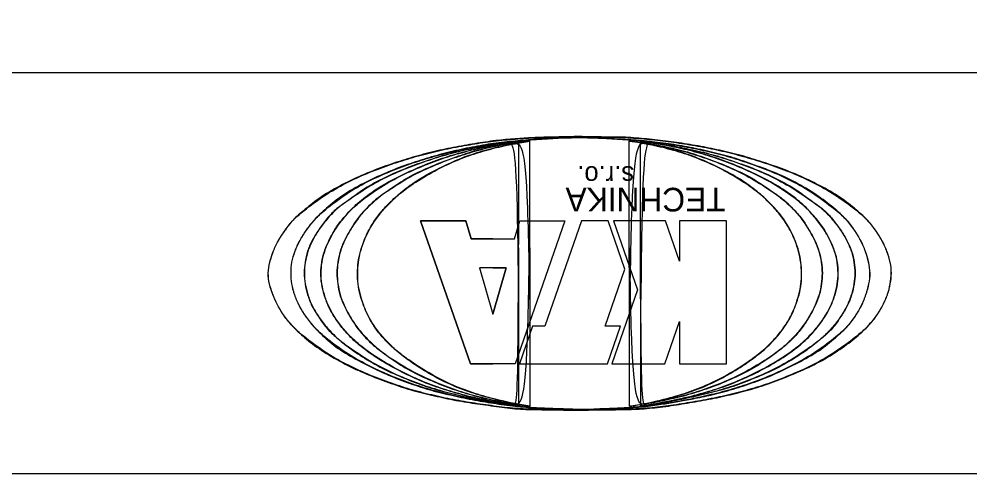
# Model space of a CAD drawing. Extents: x -728452 to -728347, y -1073107 to -1072959.
# Drawn here: x -728436.11 to -728412.4, y -1073034.8 to -1073023.46 of the extents above; entities that cross this region are included whole.
import ezdxf

# ---------------------------------------------------------------- set-up
doc = ezdxf.new("R2010")
doc.units = 0
doc.layers.add('Dočasný_nad_1_rok', color=7, linetype='Continuous')
doc.layers.add('Dočasný_nad_1_rok_PUPFL', color=7, linetype='Continuous')

msp = doc.modelspace()

# ---------------------------------------------------------------- linework, layer by layer
at = {"layer": 'Dočasný_nad_1_rok'}
msp.add_line((-728424.294, -1073032.056), (-728424.851, -1073032.056), dxfattribs=at)
for points in [[(-728424.294, -1073028.942), (-728424.836, -1073028.942), (-728424.968, -1073028.486), (-728426.094, -1073028.487), (-728424.851, -1073032.056), (-728424.294, -1073032.056)], [(-728424.851, -1073032.056), (-728426.094, -1073028.487), (-728424.968, -1073028.486), (-728424.836, -1073028.942), (-728424.294, -1073028.942)], [(-728424.294, -1073028.942), (-728423.753, -1073028.942), (-728423.621, -1073028.486), (-728422.495, -1073028.487), (-728423.738, -1073032.056), (-728424.294, -1073032.056)], [(-728424.294, -1073028.942), (-728423.753, -1073028.942), (-728423.621, -1073028.486), (-728422.495, -1073028.487), (-728423.738, -1073032.056), (-728424.294, -1073032.056)], [(-728421.435, -1073032.056), (-728421.107, -1073031.113), (-728421.495, -1073031.113), (-728421.001, -1073029.693), (-728421.421, -1073028.486), (-728422.085, -1073028.486), (-728423, -1073031.113), (-728423.302, -1073031.113), (-728423.63, -1073032.056), (-728421.435, -1073032.056)], [(-728421.435, -1073032.056), (-728421.107, -1073031.113), (-728421.495, -1073031.113), (-728421.001, -1073029.693), (-728421.421, -1073028.486), (-728422.085, -1073028.486), (-728423, -1073031.113), (-728423.302, -1073031.113), (-728423.63, -1073032.056), (-728421.435, -1073032.056)], [(-728418.466, -1073032.056), (-728418.466, -1073028.486), (-728419.635, -1073028.486), (-728419.635, -1073029.492), (-728419.985, -1073028.486), (-728421.285, -1073028.486), (-728420.685, -1073030.209), (-728421.328, -1073032.056), (-728420.003, -1073032.056), (-728419.635, -1073030.998), (-728419.635, -1073032.056), (-728418.466, -1073032.056)], [(-728418.466, -1073032.056), (-728418.466, -1073028.486), (-728419.635, -1073028.486), (-728419.635, -1073029.492), (-728419.985, -1073028.486), (-728421.285, -1073028.486), (-728420.685, -1073030.209), (-728421.328, -1073032.056), (-728420.003, -1073032.056), (-728419.635, -1073030.998), (-728419.635, -1073032.056), (-728418.466, -1073032.056)], [(-728424.294, -1073029.665), (-728424.626, -1073029.665), (-728424.294, -1073030.813)], [(-728424.294, -1073029.665), (-728424.626, -1073029.665), (-728424.294, -1073030.813)], [(-728424.294, -1073029.665), (-728423.962, -1073029.665), (-728424.294, -1073030.813)], [(-728424.294, -1073030.813), (-728423.962, -1073029.665), (-728424.294, -1073029.665)]]:
    msp.add_lwpolyline(points, dxfattribs=at)
for points in [[(-728423.358, -1073026.421), (-728423.485, -1073026.428), (-728423.79, -1073026.45), (-728424.276, -1073026.491), (-728424.81, -1073026.579), (-728425.348, -1073026.67), (-728425.885, -1073026.792), (-728426.423, -1073026.94), (-728426.96, -1073027.117), (-728427.498, -1073027.323), (-728428.038, -1073027.576), (-728428.59, -1073027.889), (-728428.983, -1073028.211), (-728429.3, -1073028.476), (-728429.469, -1073028.716), (-728429.656, -1073028.975), (-728429.776, -1073029.251), (-728429.866, -1073029.519), (-728429.918, -1073029.791), (-728429.881, -1073030.068), (-728429.779, -1073030.334), (-728429.665, -1073030.608), (-728429.497, -1073030.882), (-728429.302, -1073031.107), (-728429, -1073031.403), (-728428.589, -1073031.714), (-728428.042, -1073032.034), (-728427.504, -1073032.292), (-728426.96, -1073032.493), (-728426.428, -1073032.686), (-728425.885, -1073032.82), (-728425.349, -1073032.944), (-728424.808, -1073033.035), (-728424.271, -1073033.105), (-728423.738, -1073033.188), (-728423.202, -1073033.194), (-728422.666, -1073033.205), (-728422.309, -1073033.208), (-728422.13, -1073033.209)], [(-728422.13, -1073033.209), (-728421.524, -1073033.201), (-728421.057, -1073033.194), (-728420.521, -1073033.172), (-728419.985, -1073033.116), (-728419.45, -1073033.032), (-728418.912, -1073032.939), (-728418.377, -1073032.824), (-728417.841, -1073032.684), (-728417.303, -1073032.509), (-728416.767, -1073032.295), (-728416.234, -1073032.049), (-728415.697, -1073031.731), (-728415.161, -1073031.327), (-728414.953, -1073031.133), (-728414.734, -1073030.864), (-728414.572, -1073030.597), (-728414.451, -1073030.328), (-728414.386, -1073030.061), (-728414.356, -1073029.793), (-728414.384, -1073029.529), (-728414.465, -1073029.258), (-728414.586, -1073028.988), (-728414.754, -1073028.722), (-728414.97, -1073028.453), (-728415.161, -1073028.274), (-728415.697, -1073027.868), (-728416.233, -1073027.565), (-728416.763, -1073027.318), (-728417.305, -1073027.113), (-728417.843, -1073026.939), (-728418.376, -1073026.793), (-728418.909, -1073026.675), (-728419.447, -1073026.577), (-728419.985, -1073026.501), (-728420.523, -1073026.442), (-728421.054, -1073026.406), (-728421.594, -1073026.4), (-728422.13, -1073026.391), (-728422.666, -1073026.4), (-728423.203, -1073026.414), (-728423.739, -1073026.447), (-728424.272, -1073026.498), (-728424.81, -1073026.579), (-728425.345, -1073026.674), (-728425.881, -1073026.795), (-728426.419, -1073026.944), (-728426.955, -1073027.12), (-728427.491, -1073027.328), (-728428.024, -1073027.577), (-728428.564, -1073027.893), (-728429.103, -1073028.311), (-728429.263, -1073028.454), (-728429.473, -1073028.72), (-728429.65, -1073028.987), (-728429.774, -1073029.257), (-728429.861, -1073029.524), (-728429.904, -1073029.793), (-728429.872, -1073030.06), (-728429.78, -1073030.329), (-728429.659, -1073030.603), (-728429.499, -1073030.864), (-728429.272, -1073031.133), (-728429.106, -1073031.296), (-728428.565, -1073031.715), (-728428.029, -1073032.032), (-728427.496, -1073032.286), (-728426.958, -1073032.493), (-728426.419, -1073032.678), (-728425.886, -1073032.818), (-728425.346, -1073032.939), (-728424.807, -1073033.031), (-728424.268, -1073033.107), (-728423.737, -1073033.175), (-728423.202, -1073033.194), (-728422.667, -1073033.204), (-728422.13, -1073033.209), (-728422.13, -1073033.209), (-728422.13, -1073033.209)], [(-728422.13, -1073033.194), (-728422.309, -1073033.187), (-728422.666, -1073033.173), (-728423.204, -1073033.167), (-728423.739, -1073033.109), (-728424.275, -1073033.04), (-728424.813, -1073032.951), (-728425.348, -1073032.833), (-728425.889, -1073032.704), (-728426.424, -1073032.522), (-728426.965, -1073032.316), (-728427.499, -1073032.051), (-728428.056, -1073031.752), (-728428.468, -1073031.424), (-728428.773, -1073031.118), (-728428.965, -1073030.876), (-728429.13, -1073030.605), (-728429.252, -1073030.336), (-728429.316, -1073030.062), (-728429.34, -1073029.792), (-728429.319, -1073029.519), (-728429.238, -1073029.25), (-728429.118, -1073028.979), (-728428.946, -1073028.711), (-728428.764, -1073028.473), (-728428.455, -1073028.183), (-728428.056, -1073027.853), (-728427.503, -1073027.541), (-728426.962, -1073027.291), (-728426.424, -1073027.082), (-728425.885, -1073026.913), (-728425.349, -1073026.764), (-728424.811, -1073026.653), (-728424.275, -1073026.555), (-728423.737, -1073026.502), (-728423.202, -1073026.456), (-728422.666, -1073026.422), (-728422.13, -1073026.404), (-728421.593, -1073026.424), (-728421.057, -1073026.463), (-728420.52, -1073026.492), (-728419.983, -1073026.556), (-728419.446, -1073026.643), (-728418.909, -1073026.756), (-728418.37, -1073026.889), (-728417.837, -1073027.074), (-728417.295, -1073027.268), (-728416.752, -1073027.514), (-728416.213, -1073027.841), (-728415.79, -1073028.162), (-728415.467, -1073028.457), (-728415.274, -1073028.709), (-728415.114, -1073028.981), (-728414.994, -1073029.251), (-728414.919, -1073029.521), (-728414.872, -1073029.792), (-728414.913, -1073030.064), (-728414.983, -1073030.335), (-728415.096, -1073030.606), (-728415.255, -1073030.875), (-728415.448, -1073031.139), (-728415.783, -1073031.437), (-728416.206, -1073031.773), (-728416.761, -1073032.069), (-728417.295, -1073032.329), (-728417.834, -1073032.538), (-728418.372, -1073032.71), (-728418.91, -1073032.848), (-728419.368, -1073032.939), (-728419.726, -1073033.004), (-728420.083, -1073033.062), (-728420.52, -1073033.126), (-728421.057, -1073033.16), (-728421.593, -1073033.182), (-728421.951, -1073033.19), (-728422.13, -1073033.194)], [(-728422.13, -1073033.194), (-728421.593, -1073033.18), (-728421.057, -1073033.158), (-728420.522, -1073033.119), (-728419.986, -1073033.046), (-728419.744, -1073033.006), (-728419.45, -1073032.953), (-728418.913, -1073032.843), (-728418.377, -1073032.706), (-728417.84, -1073032.534), (-728417.304, -1073032.324), (-728416.767, -1073032.068), (-728416.234, -1073031.768), (-728415.698, -1073031.358), (-728415.459, -1073031.133), (-728415.254, -1073030.864), (-728415.1, -1073030.598), (-728414.987, -1073030.328), (-728414.917, -1073030.061), (-728414.886, -1073029.792), (-728414.923, -1073029.525), (-728414.999, -1073029.258), (-728415.116, -1073028.989), (-728415.274, -1073028.721), (-728415.484, -1073028.452), (-728415.698, -1073028.25), (-728416.233, -1073027.841), (-728416.767, -1073027.52), (-728417.303, -1073027.273), (-728417.839, -1073027.074), (-728418.376, -1073026.896), (-728418.912, -1073026.759), (-728419.448, -1073026.647), (-728419.985, -1073026.559), (-728420.521, -1073026.498), (-728421.057, -1073026.461), (-728421.594, -1073026.427), (-728422.13, -1073026.41), (-728422.665, -1073026.424), (-728423.203, -1073026.458), (-728423.736, -1073026.503), (-728424.272, -1073026.562), (-728424.809, -1073026.655), (-728425.345, -1073026.77), (-728425.881, -1073026.915), (-728426.419, -1073027.087), (-728426.955, -1073027.294), (-728427.49, -1073027.544), (-728428.028, -1073027.857), (-728428.563, -1073028.286), (-728428.735, -1073028.453), (-728428.948, -1073028.722), (-728429.114, -1073028.988), (-728429.234, -1073029.257), (-728429.31, -1073029.524), (-728429.333, -1073029.79), (-728429.31, -1073030.06), (-728429.246, -1073030.327), (-728429.128, -1073030.596), (-728428.965, -1073030.864), (-728428.752, -1073031.133), (-728428.564, -1073031.324), (-728428.028, -1073031.747), (-728427.491, -1073032.052), (-728426.955, -1073032.31), (-728426.419, -1073032.52), (-728425.882, -1073032.697), (-728425.346, -1073032.832), (-728424.81, -1073032.947), (-728424.273, -1073033.037), (-728423.737, -1073033.107), (-728423.203, -1073033.159), (-728422.667, -1073033.175), (-728422.13, -1073033.194), (-728422.13, -1073033.194), (-728422.13, -1073033.194)], [(-728423.648, -1073026.51), (-728423.751, -1073026.519), (-728423.961, -1073026.536), (-728424.35, -1073026.596), (-728424.815, -1073026.691), (-728425.357, -1073026.807), (-728425.891, -1073026.978), (-728426.43, -1073027.164), (-728426.97, -1073027.397), (-728427.517, -1073027.69), (-728427.898, -1073027.991), (-728428.237, -1073028.214), (-728428.437, -1073028.44), (-728428.642, -1073028.713), (-728428.801, -1073028.982), (-728428.924, -1073029.247), (-728428.979, -1073029.522), (-728429.009, -1073029.792), (-728428.98, -1073030.063), (-728428.918, -1073030.335), (-728428.813, -1073030.61), (-728428.647, -1073030.872), (-728428.455, -1073031.156), (-728428.236, -1073031.366), (-728427.915, -1073031.628), (-728427.512, -1073031.91), (-728426.969, -1073032.216), (-728426.426, -1073032.444), (-728425.891, -1073032.648), (-728425.351, -1073032.793), (-728424.81, -1073032.914), (-728424.275, -1073033.021), (-728423.887, -1073033.09), (-728423.678, -1073033.102), (-728423.65, -1073033.104)], [(-728423.648, -1073026.51), (-728423.956, -1073026.539), (-728424.277, -1073026.586), (-728424.813, -1073026.691), (-728425.352, -1073026.815), (-728425.889, -1073026.979), (-728426.423, -1073027.168), (-728426.956, -1073027.4), (-728427.494, -1073027.698), (-728428.033, -1073028.079), (-728428.178, -1073028.181), (-728428.441, -1073028.452), (-728428.644, -1073028.726), (-728428.799, -1073028.989), (-728428.914, -1073029.254), (-728428.975, -1073029.526), (-728428.999, -1073029.794), (-728428.975, -1073030.057), (-728428.912, -1073030.33), (-728428.807, -1073030.6), (-728428.649, -1073030.865), (-728428.457, -1073031.133), (-728428.184, -1073031.406), (-728428.037, -1073031.527), (-728427.494, -1073031.909), (-728426.953, -1073032.211), (-728426.418, -1073032.443), (-728425.89, -1073032.638), (-728425.342, -1073032.791), (-728424.811, -1073032.912), (-728424.272, -1073033.02), (-728423.734, -1073033.099), (-728423.65, -1073033.104), (-728423.648, -1073026.51), (-728423.65, -1073033.104)], [(-728423.65, -1073033.104), (-728423.843, -1073033.075), (-728424.232, -1073033.017), (-728424.8, -1073032.9), (-728425.353, -1073032.748), (-728425.893, -1073032.569), (-728426.429, -1073032.333), (-728426.97, -1073032.049), (-728427.444, -1073031.74), (-728427.816, -1073031.429), (-728428.064, -1073031.143), (-728428.258, -1073030.877), (-728428.403, -1073030.606), (-728428.506, -1073030.335), (-728428.568, -1073030.063), (-728428.586, -1073029.791), (-728428.567, -1073029.521), (-728428.499, -1073029.25), (-728428.383, -1073028.983), (-728428.242, -1073028.708), (-728428.04, -1073028.443), (-728427.796, -1073028.165), (-728427.436, -1073027.855), (-728426.97, -1073027.551), (-728426.426, -1073027.277), (-728425.887, -1073027.048), (-728425.352, -1073026.857), (-728424.814, -1073026.713), (-728424.328, -1073026.614), (-728423.939, -1073026.55), (-728423.73, -1073026.521), (-728423.648, -1073026.51)], [(-728423.65, -1073033.104), (-728424.229, -1073033.012), (-728424.81, -1073032.891), (-728425.349, -1073032.744), (-728425.887, -1073032.562), (-728426.418, -1073032.331), (-728426.954, -1073032.047), (-728427.491, -1073031.691), (-728427.828, -1073031.402), (-728428.067, -1073031.131), (-728428.256, -1073030.866), (-728428.398, -1073030.601), (-728428.501, -1073030.329), (-728428.562, -1073030.058), (-728428.58, -1073029.793), (-728428.559, -1073029.523), (-728428.493, -1073029.257), (-728428.383, -1073028.99), (-728428.238, -1073028.719), (-728428.044, -1073028.454), (-728427.804, -1073028.186), (-728427.486, -1073027.908), (-728426.955, -1073027.556), (-728426.416, -1073027.28), (-728425.881, -1073027.052), (-728425.345, -1073026.863), (-728424.811, -1073026.718), (-728424.274, -1073026.607), (-728423.893, -1073026.544), (-728423.648, -1073026.51), (-728423.65, -1073033.104), (-728423.648, -1073026.51)], [(-728423.369, -1073026.502), (-728423.492, -1073026.512), (-728423.797, -1073026.539), (-728424.276, -1073026.641), (-728424.817, -1073026.763), (-728425.35, -1073026.948), (-728425.891, -1073027.156), (-728426.44, -1073027.416), (-728426.844, -1073027.702), (-728427.203, -1073027.939), (-728427.44, -1073028.174), (-728427.683, -1073028.436), (-728427.849, -1073028.718), (-728428.003, -1073028.98), (-728428.106, -1073029.25), (-728428.163, -1073029.52), (-728428.193, -1073029.791), (-728428.16, -1073030.062), (-728428.118, -1073030.335), (-728428.007, -1073030.604), (-728427.864, -1073030.871), (-728427.69, -1073031.146), (-728427.463, -1073031.42), (-728427.207, -1073031.648), (-728426.858, -1073031.911), (-728426.436, -1073032.188), (-728425.893, -1073032.454), (-728425.354, -1073032.664), (-728424.818, -1073032.84), (-728424.278, -1073032.963), (-728423.797, -1073033.062), (-728423.492, -1073033.097), (-728423.369, -1073033.111)], [(-728423.369, -1073026.502), (-728423.737, -1073026.54), (-728424.276, -1073026.642), (-728424.807, -1073026.771), (-728425.346, -1073026.95), (-728425.884, -1073027.16), (-728426.417, -1073027.423), (-728426.954, -1073027.774), (-728427.157, -1073027.916), (-728427.449, -1073028.186), (-728427.68, -1073028.452), (-728427.851, -1073028.721), (-728427.998, -1073028.989), (-728428.101, -1073029.257), (-728428.159, -1073029.52), (-728428.182, -1073029.792), (-728428.159, -1073030.062), (-728428.109, -1073030.328), (-728428.006, -1073030.594), (-728427.862, -1073030.867), (-728427.691, -1073031.133), (-728427.467, -1073031.402), (-728427.173, -1073031.67), (-728426.952, -1073031.838), (-728426.418, -1073032.183), (-728425.884, -1073032.449), (-728425.345, -1073032.662), (-728424.813, -1073032.833), (-728424.277, -1073032.961), (-728423.737, -1073033.065), (-728423.369, -1073033.111), (-728423.369, -1073026.502), (-728423.369, -1073033.111)], [(-728423.369, -1073033.111), (-728423.492, -1073033.093), (-728423.796, -1073033.049), (-728424.276, -1073032.931), (-728424.819, -1073032.787), (-728425.36, -1073032.576), (-728425.899, -1073032.298), (-728426.371, -1073031.989), (-728426.758, -1073031.692), (-728427.029, -1073031.412), (-728427.242, -1073031.145), (-728427.403, -1073030.873), (-728427.519, -1073030.602), (-728427.606, -1073030.332), (-728427.662, -1073030.063), (-728427.67, -1073029.792), (-728427.655, -1073029.522), (-728427.603, -1073029.251), (-728427.507, -1073028.985), (-728427.389, -1073028.711), (-728427.219, -1073028.444), (-728427.006, -1073028.173), (-728426.736, -1073027.907), (-728426.368, -1073027.6), (-728425.899, -1073027.308), (-728425.358, -1073027.04), (-728424.82, -1073026.821), (-728424.278, -1073026.67), (-728423.794, -1073026.57), (-728423.492, -1073026.522), (-728423.369, -1073026.502)], [(-728423.369, -1073033.111), (-728423.737, -1073033.053), (-728424.273, -1073032.93), (-728424.811, -1073032.778), (-728425.347, -1073032.57), (-728425.883, -1073032.295), (-728426.419, -1073031.947), (-728426.771, -1073031.667), (-728427.031, -1073031.401), (-728427.242, -1073031.132), (-728427.4, -1073030.866), (-728427.517, -1073030.597), (-728427.602, -1073030.329), (-728427.655, -1073030.06), (-728427.667, -1073029.794), (-728427.649, -1073029.525), (-728427.596, -1073029.256), (-728427.506, -1073028.99), (-728427.385, -1073028.722), (-728427.219, -1073028.453), (-728427.011, -1073028.19), (-728426.741, -1073027.919), (-728426.419, -1073027.653), (-728425.884, -1073027.311), (-728425.348, -1073027.043), (-728424.812, -1073026.83), (-728424.271, -1073026.675), (-728423.738, -1073026.563), (-728423.369, -1073026.502), (-728423.369, -1073033.111), (-728423.369, -1073026.502)], [(-728422.13, -1073033.209), (-728421.928, -1073033.206), (-728421.57, -1073033.2), (-728421.034, -1073033.196), (-728420.52, -1073033.179), (-728419.983, -1073033.121), (-728419.449, -1073033.032), (-728418.911, -1073032.943), (-728418.374, -1073032.827), (-728417.835, -1073032.688), (-728417.297, -1073032.513), (-728416.763, -1073032.297), (-728416.218, -1073032.054), (-728415.678, -1073031.732), (-728415.255, -1073031.416), (-728414.933, -1073031.124), (-728414.735, -1073030.877), (-728414.57, -1073030.605), (-728414.442, -1073030.338), (-728414.384, -1073030.063), (-728414.344, -1073029.795), (-728414.376, -1073029.521), (-728414.462, -1073029.252), (-728414.581, -1073028.978), (-728414.756, -1073028.712), (-728414.944, -1073028.467), (-728415.262, -1073028.181), (-728415.672, -1073027.863), (-728416.221, -1073027.564), (-728416.758, -1073027.311), (-728417.299, -1073027.111), (-728417.837, -1073026.936), (-728418.372, -1073026.788), (-728418.909, -1073026.672), (-728419.445, -1073026.573), (-728419.984, -1073026.498), (-728420.52, -1073026.44), (-728421.056, -1073026.397), (-728421.592, -1073026.404), (-728422.13, -1073026.385), (-728422.666, -1073026.401), (-728423.076, -1073026.407), (-728423.307, -1073026.418), (-728423.358, -1073026.421)], [(-728420.89, -1073026.502), (-728420.767, -1073026.512), (-728420.462, -1073026.539), (-728419.983, -1073026.641), (-728419.442, -1073026.763), (-728418.909, -1073026.948), (-728418.368, -1073027.156), (-728417.819, -1073027.416), (-728417.415, -1073027.702), (-728417.056, -1073027.939), (-728416.819, -1073028.174), (-728416.576, -1073028.436), (-728416.41, -1073028.718), (-728416.257, -1073028.98), (-728416.153, -1073029.25), (-728416.096, -1073029.52), (-728416.066, -1073029.791), (-728416.099, -1073030.062), (-728416.141, -1073030.335), (-728416.252, -1073030.604), (-728416.395, -1073030.871), (-728416.569, -1073031.146), (-728416.796, -1073031.42), (-728417.052, -1073031.648), (-728417.401, -1073031.911), (-728417.823, -1073032.188), (-728418.367, -1073032.454), (-728418.906, -1073032.664), (-728419.441, -1073032.84), (-728419.981, -1073032.963), (-728420.462, -1073033.062), (-728420.767, -1073033.097), (-728420.891, -1073033.111)], [(-728420.891, -1073033.111), (-728420.767, -1073033.093), (-728420.463, -1073033.049), (-728419.983, -1073032.931), (-728419.44, -1073032.787), (-728418.9, -1073032.576), (-728418.36, -1073032.298), (-728417.888, -1073031.989), (-728417.501, -1073031.692), (-728417.231, -1073031.412), (-728417.018, -1073031.145), (-728416.856, -1073030.873), (-728416.74, -1073030.602), (-728416.653, -1073030.332), (-728416.597, -1073030.063), (-728416.589, -1073029.792), (-728416.604, -1073029.522), (-728416.657, -1073029.251), (-728416.752, -1073028.985), (-728416.87, -1073028.711), (-728417.04, -1073028.444), (-728417.253, -1073028.173), (-728417.523, -1073027.907), (-728417.891, -1073027.6), (-728418.36, -1073027.308), (-728418.902, -1073027.04), (-728419.439, -1073026.821), (-728419.981, -1073026.67), (-728420.465, -1073026.57), (-728420.767, -1073026.522), (-728420.89, -1073026.502)], [(-728420.89, -1073026.502), (-728420.522, -1073026.54), (-728419.983, -1073026.642), (-728419.452, -1073026.771), (-728418.913, -1073026.95), (-728418.376, -1073027.16), (-728417.842, -1073027.423), (-728417.305, -1073027.774), (-728417.102, -1073027.916), (-728416.811, -1073028.186), (-728416.579, -1073028.452), (-728416.408, -1073028.721), (-728416.261, -1073028.989), (-728416.158, -1073029.257), (-728416.101, -1073029.52), (-728416.077, -1073029.792), (-728416.1, -1073030.062), (-728416.15, -1073030.328), (-728416.253, -1073030.594), (-728416.397, -1073030.867), (-728416.568, -1073031.133), (-728416.792, -1073031.402), (-728417.086, -1073031.67), (-728417.307, -1073031.838), (-728417.841, -1073032.183), (-728418.375, -1073032.449), (-728418.914, -1073032.662), (-728419.446, -1073032.833), (-728419.982, -1073032.961), (-728420.522, -1073033.065), (-728420.891, -1073033.111), (-728420.89, -1073026.502), (-728420.891, -1073033.111)], [(-728420.891, -1073033.111), (-728420.522, -1073033.053), (-728419.986, -1073032.93), (-728419.448, -1073032.778), (-728418.913, -1073032.57), (-728418.376, -1073032.295), (-728417.841, -1073031.947), (-728417.489, -1073031.667), (-728417.228, -1073031.401), (-728417.018, -1073031.132), (-728416.86, -1073030.866), (-728416.743, -1073030.597), (-728416.657, -1073030.329), (-728416.604, -1073030.06), (-728416.593, -1073029.794), (-728416.61, -1073029.525), (-728416.663, -1073029.256), (-728416.754, -1073028.99), (-728416.874, -1073028.722), (-728417.041, -1073028.453), (-728417.248, -1073028.19), (-728417.518, -1073027.919), (-728417.84, -1073027.653), (-728418.375, -1073027.311), (-728418.911, -1073027.043), (-728419.447, -1073026.83), (-728419.988, -1073026.675), (-728420.522, -1073026.563), (-728420.89, -1073026.502), (-728420.891, -1073033.111), (-728420.89, -1073026.502)], [(-728420.609, -1073033.104), (-728420.416, -1073033.075), (-728420.027, -1073033.017), (-728419.459, -1073032.9), (-728418.906, -1073032.748), (-728418.366, -1073032.569), (-728417.83, -1073032.333), (-728417.289, -1073032.049), (-728416.815, -1073031.74), (-728416.443, -1073031.429), (-728416.196, -1073031.143), (-728416.001, -1073030.877), (-728415.857, -1073030.606), (-728415.753, -1073030.335), (-728415.691, -1073030.063), (-728415.673, -1073029.791), (-728415.692, -1073029.521), (-728415.76, -1073029.25), (-728415.876, -1073028.983), (-728416.017, -1073028.708), (-728416.219, -1073028.443), (-728416.464, -1073028.165), (-728416.823, -1073027.855), (-728417.289, -1073027.551), (-728417.833, -1073027.277), (-728418.372, -1073027.048), (-728418.907, -1073026.857), (-728419.445, -1073026.713), (-728419.932, -1073026.614), (-728420.32, -1073026.55), (-728420.529, -1073026.521), (-728420.611, -1073026.51)], [(-728420.611, -1073026.51), (-728420.508, -1073026.519), (-728420.298, -1073026.536), (-728419.909, -1073026.596), (-728419.444, -1073026.691), (-728418.902, -1073026.807), (-728418.368, -1073026.978), (-728417.829, -1073027.164), (-728417.289, -1073027.397), (-728416.742, -1073027.69), (-728416.361, -1073027.991), (-728416.023, -1073028.214), (-728415.822, -1073028.44), (-728415.617, -1073028.713), (-728415.459, -1073028.982), (-728415.335, -1073029.247), (-728415.28, -1073029.522), (-728415.25, -1073029.792), (-728415.279, -1073030.063), (-728415.341, -1073030.335), (-728415.446, -1073030.61), (-728415.613, -1073030.872), (-728415.804, -1073031.156), (-728416.023, -1073031.366), (-728416.344, -1073031.628), (-728416.747, -1073031.91), (-728417.29, -1073032.216), (-728417.834, -1073032.444), (-728418.368, -1073032.648), (-728418.909, -1073032.793), (-728419.45, -1073032.914), (-728419.985, -1073033.021), (-728420.372, -1073033.09), (-728420.581, -1073033.102), (-728420.609, -1073033.104)], [(-728420.611, -1073026.51), (-728420.303, -1073026.539), (-728419.983, -1073026.586), (-728419.446, -1073026.691), (-728418.908, -1073026.815), (-728418.37, -1073026.979), (-728417.836, -1073027.168), (-728417.303, -1073027.4), (-728416.765, -1073027.698), (-728416.226, -1073028.079), (-728416.082, -1073028.181), (-728415.819, -1073028.452), (-728415.615, -1073028.726), (-728415.46, -1073028.989), (-728415.345, -1073029.254), (-728415.284, -1073029.526), (-728415.26, -1073029.794), (-728415.284, -1073030.057), (-728415.347, -1073030.33), (-728415.452, -1073030.6), (-728415.61, -1073030.865), (-728415.802, -1073031.133), (-728416.075, -1073031.406), (-728416.222, -1073031.527), (-728416.765, -1073031.909), (-728417.307, -1073032.211), (-728417.841, -1073032.443), (-728418.369, -1073032.638), (-728418.917, -1073032.791), (-728419.448, -1073032.912), (-728419.987, -1073033.02), (-728420.525, -1073033.099), (-728420.609, -1073033.104), (-728420.611, -1073026.51), (-728420.609, -1073033.104)], [(-728420.609, -1073033.104), (-728420.03, -1073033.012), (-728419.45, -1073032.891), (-728418.911, -1073032.744), (-728418.373, -1073032.562), (-728417.842, -1073032.331), (-728417.305, -1073032.047), (-728416.768, -1073031.691), (-728416.431, -1073031.402), (-728416.192, -1073031.131), (-728416.003, -1073030.866), (-728415.861, -1073030.601), (-728415.758, -1073030.329), (-728415.698, -1073030.058), (-728415.679, -1073029.793), (-728415.7, -1073029.523), (-728415.766, -1073029.257), (-728415.876, -1073028.99), (-728416.021, -1073028.719), (-728416.215, -1073028.454), (-728416.455, -1073028.186), (-728416.773, -1073027.908), (-728417.304, -1073027.556), (-728417.843, -1073027.28), (-728418.378, -1073027.052), (-728418.914, -1073026.863), (-728419.448, -1073026.718), (-728419.985, -1073026.607), (-728420.366, -1073026.544), (-728420.611, -1073026.51), (-728420.609, -1073033.104), (-728420.611, -1073026.51)]]:
    msp.add_open_spline(points, degree=3, dxfattribs=at)
at = {"layer": 'Dočasný_nad_1_rok_PUPFL'}
msp.add_line((-728357.31, -1073024.8), (-728442.31, -1073024.8), dxfattribs=at)
msp.add_lwpolyline([(-728357.31, -1073034.8), (-728442.31, -1073034.8), (-728442.31, -1073009.8), (-728357.31, -1073009.8)], close=True, dxfattribs=at)

# ---------------------------------------------------------------- texts
at = {"layer": 'Dočasný_nad_1_rok'}
for s, height, p in [('s.r.o.', 0.4772, (-728420.769, -1073027.127)), ('TECHNIKA', 0.5898, (-728418.491, -1073027.666))]:
    msp.add_text(s, height=height, rotation=180, dxfattribs=at).set_placement(p)

doc.saveas('drawing.dxf')
